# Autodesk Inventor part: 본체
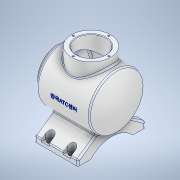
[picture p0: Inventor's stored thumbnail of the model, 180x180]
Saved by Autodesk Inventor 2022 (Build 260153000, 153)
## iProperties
Created: 2023-04
Part Number: 본체
Material: 알루미늄 6061
Document SubType Name: Modeling
Designer: Admin
Density: 2.7 g/cm^3
Appearance: 알루미늄 - 평지
Mass: 1292.15 g
Surface Area: 1061.65 cm^2
Volume: 478.573 cm^3
Author: Admin
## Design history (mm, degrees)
sketch "스케치1"
  geometry: L1 (-76.344, 0)-(85.885, 0) reference; L2 (0, -10.134)-(0, 60.805) reference; L3 (-48.168, 50)-(48.168, 50); L4 (48.168, 50)-(48.168, 0); L5 (48.168, 0)-(-48.168, 0); L6 (-48.168, 0)-(-48.168, 50); L7 (48.168, 0)-(59.832, 0); A1 r 113 centre (-53.168, 0) between (59.832, 0) and (48.168, 50); 1 further point
  constraints: 10 end point, 3 point on line, 2 horizontal, 2 parallel, 2 point on circle, 1 centre point, 1 perpendicular, 1 other
  dimensions: "d0" = 113 radius of A1; "d1" = 108 distance from line of L7.end L6; "d2" = 100 diameter of L3.start L1
revolve "회전1" sketch "스케치1" stored, may be unused: angle "d3" = 360 deg
node "작업 평면1"
sketch "스케치2"
  geometry: L1 (-39.832, -62)-(40.168, -62); L2 (40.168, -62)-(40.168, 62); L3 (40.168, 62)-(-39.832, 62); L4 (-39.832, 62)-(-39.832, -62); L5 (-39.832, -62)-(40.168, 62); L6 (40.168, -62)-(-39.832, 62); L7 (84.168, 0)-(-83.832, 0) reference; L8 (48.168, 50)-(48.168, -50) reference; 1 further point
  constraints: 12 end point, 2 midpoint, 2 parallel, 1 horizontal, 1 perpendicular
  dimensions: "d5" = 124 distance of L3.end L1.start; "d6" = 80 distance of L2.end L3.end; "d93" = 8 distance between parallel lines of L2 L8
extrude "돌출1" join sketch "스케치2" distance "d7" = 10; taper "d8" = 0 deg
sketch "스케치4"
  geometry: L1 (62, -67.515)-(62, 159.419) reference; L2 (-24.8, 77)-(148.8, 77) reference; L3 (124, 0)-(0, 0) reference; L4 (23.5, 0)-(100.5, 0); A1 r 52.096 centre (62, -35.096) between (100.5, 0) and (23.5, 0); 1 further point
  constraints: 2 end point, 2 point on circle, 2 point on line, 1 centre point, 1 collinear, 1 symmetric about line
  dimensions: "d14" = 77 distance of L4.end L4.start; "d15" = 17 distance edge to line of A1 L3
extrude "돌출3" cut sketch "스케치4" extent not by distance; stored distance "d16" = 0; taper "d17" = 0 deg
sketch "스케치5"
  geometry: C1 r 36 at (0, 0); 1 further point
  constraints: 1 centre point, 1 coincident
  dimensions: "d18" = 72 diameter of C1
extrude "돌출4" join sketch "스케치5" distance "d19" = 12; taper "d20" = 0 deg
node "작업 평면5"
sketch "스케치16"
  geometry: L1 (-62, -77)-(-62, -67) reference; L2 (-62, -67)-(-9.127, -29.978); L3 (-9.127, -29.978)-(9.127, -29.978); L4 (62, -77)-(62, -67) reference; L5 (9.127, -29.978)-(62, -67); L6 (-26.083, -67)-(-62, -67) reference; L7 (-62, -67)-(62, -67); 2 further points
  constraints: 8 end point, 1 collinear, 1 perpendicular
  dimensions: "d95" = 55 deg angle of L4 L5; "d96" = 55 deg angle of L2 L1; "d97" = 37.02189 distance between parallel lines of L7 L3
extrude "돌출8" join sketch "스케치16" stored distance "d98" = 80; taper "d99" = 0 deg
node "작업 평면2"
sketch "스케치6"
  geometry: L1 (60.168, -36)-(60.168, 36) reference; L2 (84.168, 0)-(-83.832, 0) reference; C1 r 36 at (-1.832, 0)
  constraints: 1 centre point, 1 point on line
  dimensions: "d22" = 72 diameter of C1; "d90" = 62 distance from line of C1.centre L1
extrude "돌출5" join sketch "스케치6" stored distance "d23" = 12; taper "d24" = 0 deg
sketch "스케치7"
  geometry: L1 (-84.168, 0)-(83.832, 0) reference; L2 (0, -105.4)-(0, 93.4) reference; L3 (-60.168, 36)-(-60.168, -36) reference; L4 (-60.168, 27)-(-41.168, 27); L5 (-41.168, 27)-(-41.168, 0); L6 (-41.168, 0)-(-60.168, 0); L7 (-60.168, 0)-(-60.168, 27); L8 (-41.168, 43)-(44.331, 43); L9 (44.331, 43)-(44.331, 0); L10 (44.331, 0)-(-41.168, 0); L11 (-41.168, 0)-(-41.168, 43); L12 (44.331, 0)-(52.832, 0); A1 r 113 centre (-60.168, 0) between (52.832, 0) and (44.331, 43); A2 r 113 centre (-53.168, 0) between (48.168, -50) and (48.168, 50) reference; 3 further points
  constraints: 18 end point, 6 point on line, 4 parallel, 3 horizontal, 2 perpendicular, 2 point on circle, 1 centre point
  dimensions: "d25" = 113 radius of A1; "d26" = 19 distance of L4.start L4.end; "d27" = 86 diameter of L8.start L1; "d28" = 54 diameter of L4.start L1; "d29" = 7 distance of A2.centre A1.centre
revolve "회전2" sketch "스케치7" stored, may be unused: angle "d30" = 360 deg
sketch "스케치8"
  geometry: L1 (-62, 36)-(-62, -36) reference; L2 (-86, 0)-(82, 0) reference; C1 r 27 at (0, 0)
  constraints: 1 centre point, 1 point on line
  dimensions: "d31" = 54 diameter of C1; "d92" = 62 distance from line of C1.centre L1
extrude "돌출6" cut sketch "스케치8" stored distance "d32" = 10; taper "d33" = 0 deg
sketch "스케치9"
  geometry: L1 (-69.768, 0)-(81.432, 0) reference; L2 (-40.168, 38.5)-(-40.168, 62) reference; 5 further points
  constraints: 2 symmetric about line
  dimensions: "d34" = 108 distance of point (-20.168, 54) point (-20.168, -54); "d35" = 108 distance of point (19.832, 54) point (19.832, -54); "d36" = 40 distance of point (19.832, 54) point (-20.168, 54); "d37" = 20 distance from line of L2 point (-20.168, 54)
hole "구멍1" sketch "스케치9" at (19.832, -54), (-20.168, -54), (-20.168, 54), (19.832, 54) diameter "d38" = 9; stored, may be unused: countersink angle "d42" = 90 deg, drill point angle "d44" = 118 deg; dims "d39" = 6, "d40" = 4, "d41" = 2, "d43" = 6
node "작업 평면4"
sketch "스케치12"
  geometry: L1 (26.832, -54)-(26.832, -62); L2 (39.832, -62)-(-40.168, -62) reference; L3 (12.832, -54)-(12.832, -62); L4 (-13.168, -54)-(-13.168, -62); L5 (-27.168, -54)-(-27.168, -62); L6 (26.832, -62)-(12.832, -62); L7 (-13.168, -62)-(-27.168, -62); C1 r 4.5 at (19.832, -54) reference; C2 r 4.5 at (-20.168, -54) reference; A1 r 7 centre (19.832, -54) between (26.832, -54) and (12.832, -54); A2 r 7 centre (-20.168, -54) between (-13.168, -54) and (-27.168, -54); 1 further point
  constraints: 12 end point, 4 point on circle, 4 point on line, 4 tangent, 3 parallel, 2 centre point, 2 coincident, 2 collinear, 1 vertical
  dimensions: "d51" = 14 diameter of A1; "d52" = 14 diameter of A2
extrude "돌출7" cut sketch "스케치12" stored distance "d53" = 10; taper "d54" = 0 deg
sketch "스케치13" dims "d55" = 65
  geometry: L1 (0, -102.4)-(0, 75.4) reference; 6 further points
  constraints: 1 coincident, 1 point on line, 1 vertical alignment, 7 other
  dimensions: "d58" = 360 deg dimension on point (0, 0) point (0, 32.5) (derived)
hole "구멍2" sketch "스케치13" at (0, 32.5), (-32.5, 0), (0, -32.5), (32.5, 0) diameter "d60" = 3.242; stored, may be unused: countersink angle "d64" = 90 deg, drill point angle "d66" = 118 deg; dims "d61" = 8, "d62" = 4, "d63" = 2, "d65" = 10
sketch "스케치14" dims "d67" = 65
  geometry: L1 (-86, 0)-(82, 0) reference; L2 (-62, 36)-(-62, -36) reference; 5 further points
  constraints: 2 point on line, 1 horizontal alignment, 7 other
  dimensions: "d70" = 360 deg dimension on point (0, 0) point (32.5, 0) (derived); "d91" = 62 distance from line of L2 point (0, 0)
hole "구멍3" sketch "스케치14" at (32.5, 0), (0, 32.5), (-32.5, 0), (0, -32.5) diameter "d72" = 3.242; stored, may be unused: countersink angle "d76" = 90 deg, drill point angle "d78" = 118 deg; dims "d73" = 8, "d74" = 4, "d75" = 2, "d77" = 10
sketch "스케치15"
  geometry: L1 (-20, 113)-(-20, 41) reference; L2 (-44, 77)-(124, 77) reference; 2 further points
  constraints: 1 point on line, 1 other
  dimensions: "d79" = 62 distance from line of L1 point (42, 77)
feature "엠보싱1" sketch "스케치15" dims "d80" = 0.5, "d81" = 0
fillet "모깎기1" dims "d82" = 3
fillet "모깎기5" dims "d86" = 3
chamfer "모따기1" distance "d87" = 1; stored, may be unused: second distance "d88" = 2, angle "d89" = 45 deg
fillet "모깎기6" dims "d100" = 3
fillet "모깎기7" dims "d101" = 3
fillet "모깎기8" dims "d102" = 3
sketch "스케치17"
  geometry: L1 (85.083, -10)-(64.583, -10) reference; L2 (-12.417, -10)-(64.583, -10); A1 r 52.096 centre (26.083, -45.096) between (64.583, -10) and (52.167, 0) reference; A2 r 52.096 centre (26.083, -45.096) between (64.583, -10) and (-12.417, -10); 2 further points
  constraints: 2 end point, 2 point on circle, 1 centre point, 1 coincident, 1 collinear
extrude "돌출9" cut sketch "스케치17" extent not by distance; stored distance "d103" = 0; taper "d104" = 0 deg
node "솔리드1"
mirror "미러1"
feature "A9D066F2-1C7D-4E18-AEED-F7BC21143FA4" dims "d38" = 9, "d39" = 6, "d40" = 4, "d41" = 2, "d42" = 90 deg, "d43" = 6, "d44" = 118 deg
other parameters: "d4" = -77, "d21" = 65, "d50" = -6
